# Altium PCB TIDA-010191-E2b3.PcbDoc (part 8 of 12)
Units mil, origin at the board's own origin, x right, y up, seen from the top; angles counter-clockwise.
Board outline 9842.52 x 9842.4 mil, 6 copper layers (Layer 1 - Top Layer, Layer 2 - GND Layer, Layer 3 - Signal, Layer 4 - Signal, Layer 5 - GND, Bottom Layer), stack 59.9 mil thick; 1178 components, 642 nets, 3329 pads, 2967 vias.
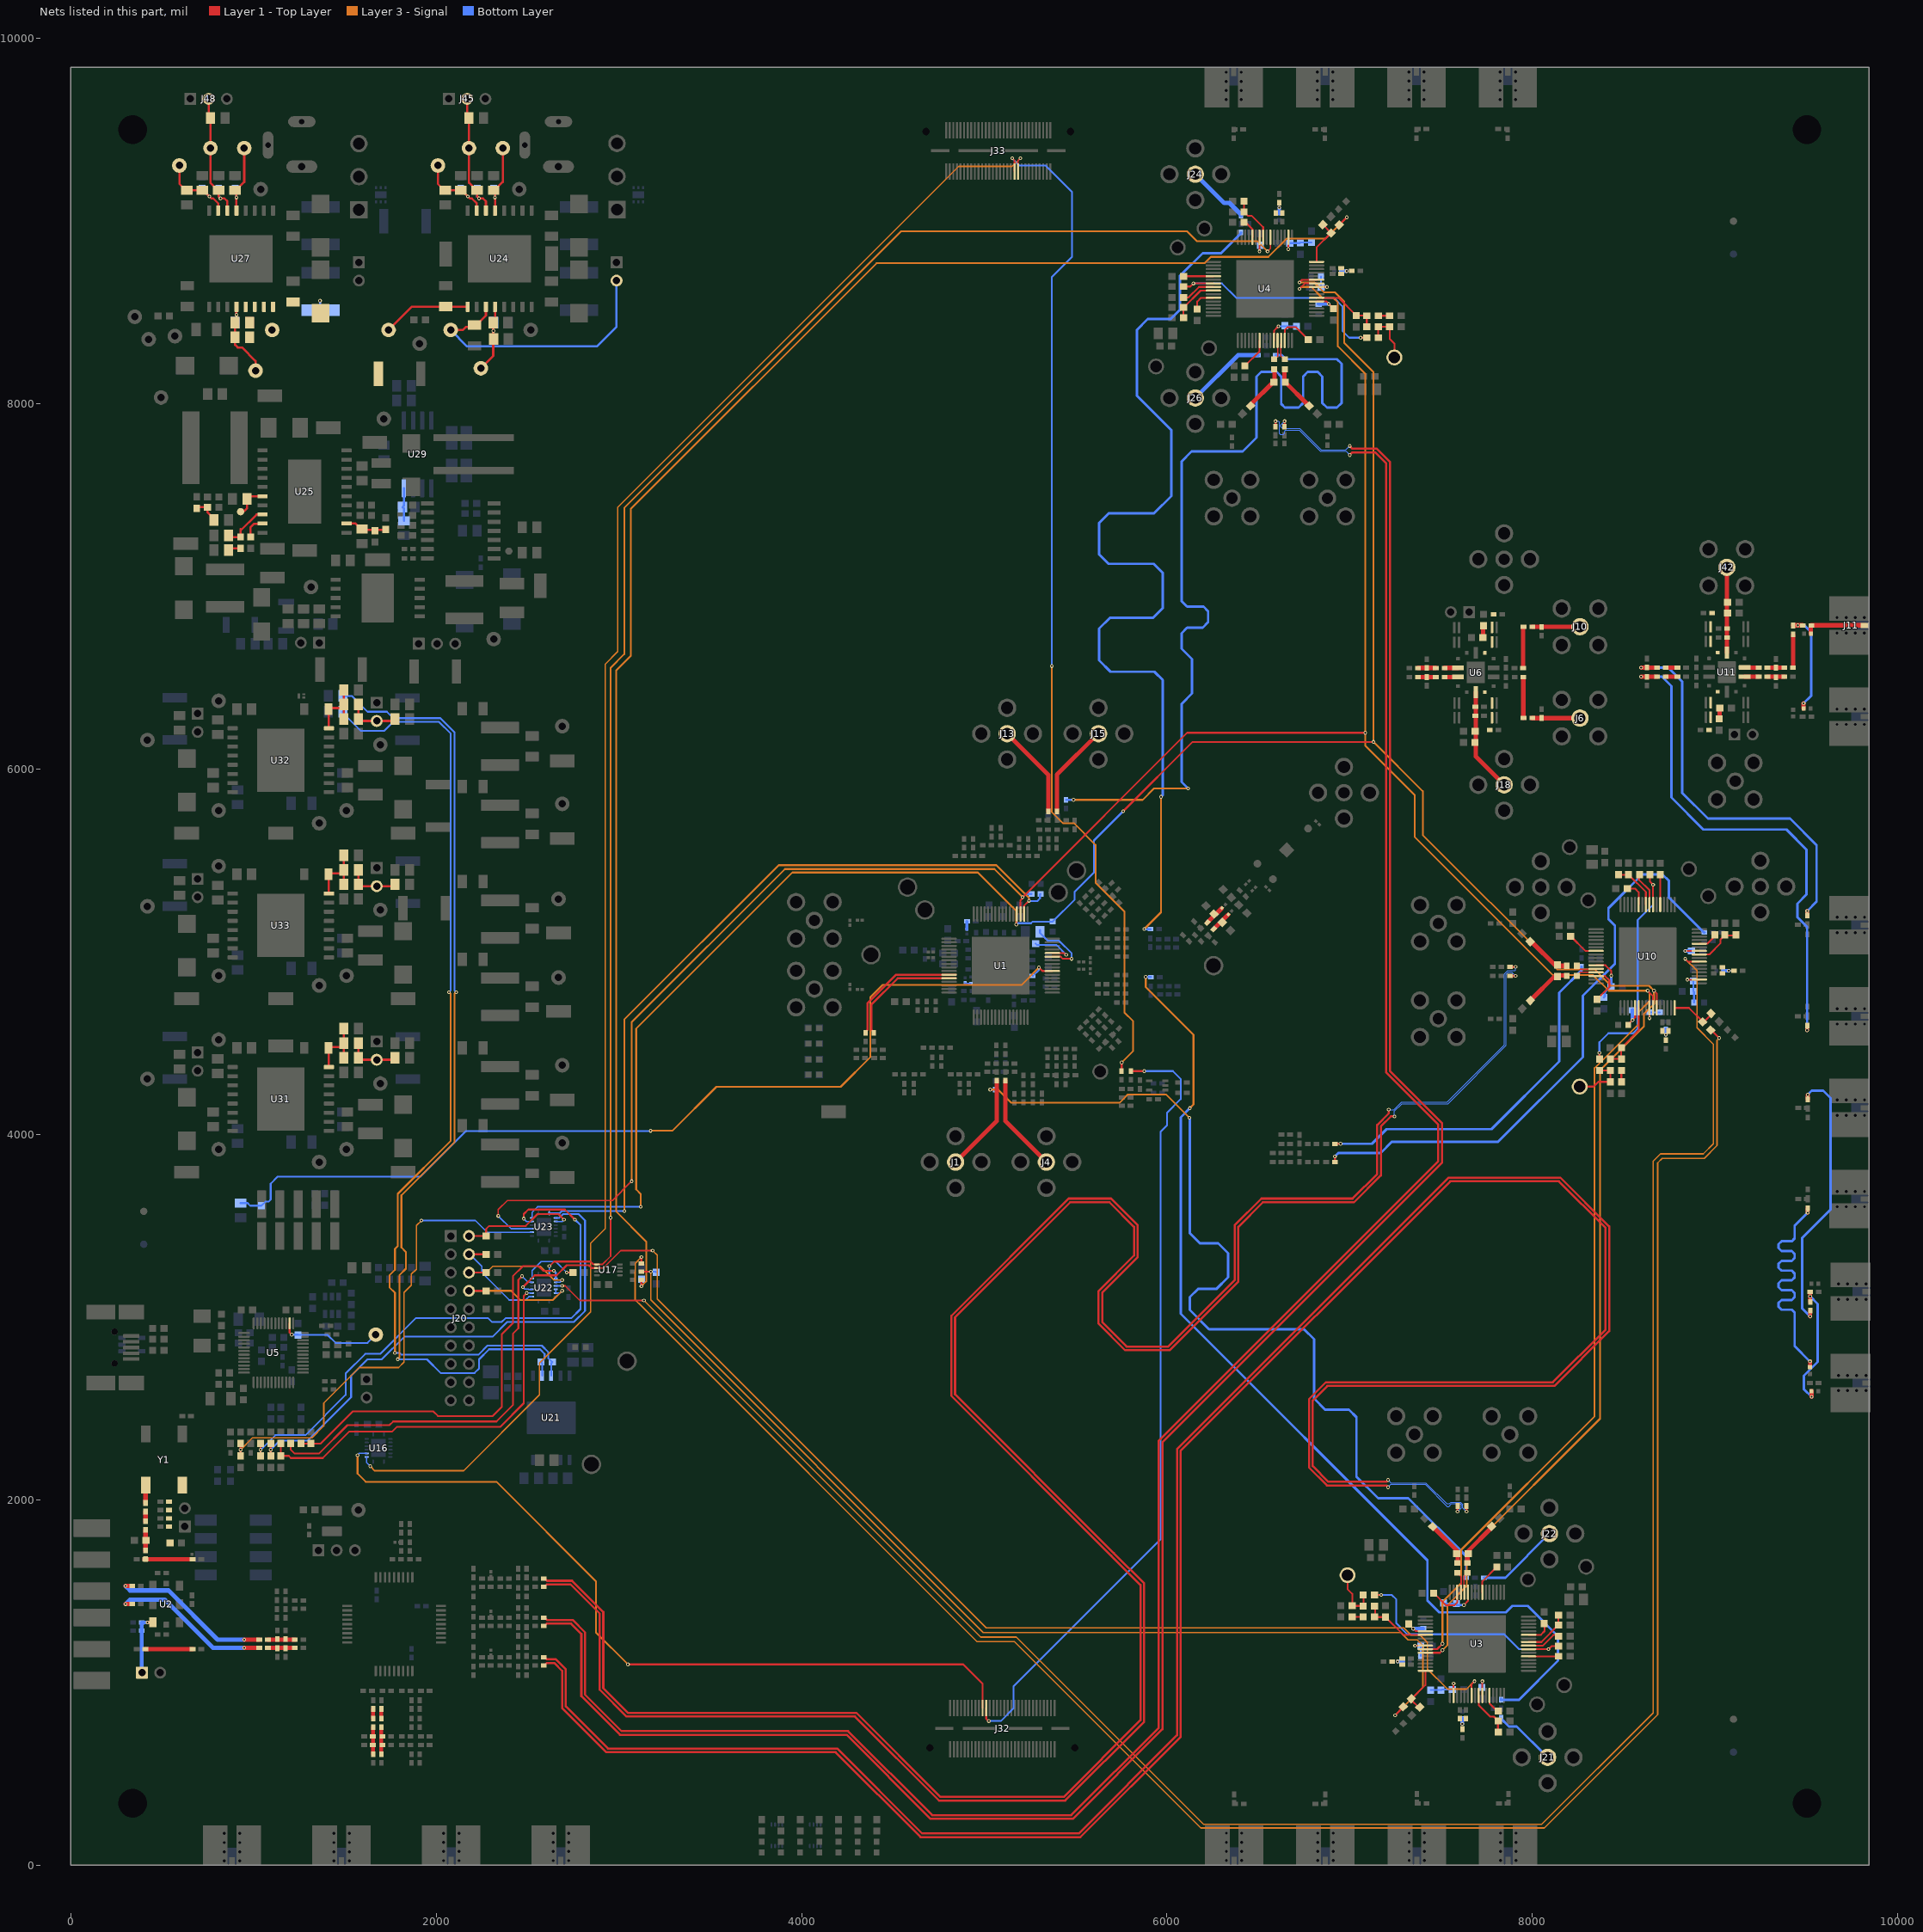
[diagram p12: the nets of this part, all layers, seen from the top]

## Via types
v1: diameter 20, hole 10, Layer 1 - Top Layer to Bottom Layer, tented both sides, 2595 vias
v2: diameter 19.68, hole 7.87, Layer 1 - Top Layer to Bottom Layer, 308 vias
v3: diameter 19.68, hole 7.87, Layer 1 - Top Layer to Bottom Layer, tented both sides, 25 vias
v4: diameter 20, hole 10, Layer 1 - Top Layer to Bottom Layer, 21 vias
v5: diameter 41, hole 25, Layer 1 - Top Layer to Bottom Layer, 10 vias
v6: diameter 24, hole 12, Layer 1 - Top Layer to Bottom Layer, tented both sides, 4 vias
v7: diameter 24, hole 8, Layer 1 - Top Layer to Bottom Layer, tented both sides, 1 vias
v8: diameter 24/24/24/24/24/24 (per signal layer), hole 8, Layer 1 - Top Layer to Bottom Layer, tented both sides, 1 vias
v9: diameter 30, hole 12, Layer 1 - Top Layer to Bottom Layer, tented both sides, 1 vias
v10: diameter 20/20/20/20/20/20 (per signal layer), hole 10, Layer 1 - Top Layer to Bottom Layer, tented both sides, 1 vias

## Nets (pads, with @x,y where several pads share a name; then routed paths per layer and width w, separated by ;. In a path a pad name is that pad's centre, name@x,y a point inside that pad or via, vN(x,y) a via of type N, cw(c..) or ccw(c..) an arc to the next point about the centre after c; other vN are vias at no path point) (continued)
ILMK04832-SP_CSb: R157.2 R187.1 U23.10 | length 2849.3
  Layer 1 - Top Layer w10: R187.1@1095,2241.5 v1(1095,2275) R157.2@1095,2309.09
  Bottom Layer w10: v1(1095,2275) 1145,2325 1297.43,2325 1535,2562.57 1535,2680 1625,2770 1702.2,2770 1826.37,2894.17 2309.17,2894.17 2390,2975 2755,2975 2815,3035 2815,3530 2780,3565 2695,3565 2674.49,3544.49 2655.24,3544.49 U23.10@2654.96,3544.21
ILMK_LMX_CLK: R154.2 R185.1 U23.3 | length 2680.8
  Layer 1 - Top Layer w10: R185.1@930,2241.5 v1(930,2275) R154.2@930,2309.09
  Layer 3 - Signal w8: v1(930,2275) 995,2340 1320,2340 1385,2405 1385,2530 1580,2725 1795,2725 1825,2755 1825,3135 1865,3175 1865,3236.5 1892.2,3263.7 1892.2,3502.2 v1(1920,3530)
  Bottom Layer w8: v1(1920,3530) 2215,3530 2279.53,3465.47 U23.3@2525.04,3465.47
ILMK_LMX_DATA: R156.2 R186.1 U23.6 | length 3113.9
  Layer 1 - Top Layer w10: R186.1@1040,2241.5 v1(1040,2275) R156.2@1040,2309.09 ; v1(2480,3540) 2480,3565 2505,3590 2705,3590 v1(2760,3535)
  Bottom Layer w8: v1(2480,3540) 2495.47,3524.53 U23.6@2525.04,3524.53
  Bottom Layer w10: v1(1040,2275) 1120,2355 1285,2355 1505,2575 1505,2692.43 1612.57,2800 1693.5,2800 1888.5,2995 2285,2995 2305,2975 2360,2975 2380,2995 2740,2995 2790,3045 2790,3505 v1(2760,3535)
ILMX1_CSB: R158.2 R188.1 U22.3 | length 2165.7
  Layer 1 - Top Layer w10: R158.2@1150,2309.09 R188.1@1150,2241.5 1193.5,2241.5 1205,2230 1380,2230 1525,2375 1760,2375 1785,2400 2350,2400 2480,2530 2480,3117.05 v1(2496.48,3133.52)
  Bottom Layer w8: v1(2496.48,3133.52) 2496.97,3133.03 U22.3@2525.04,3133.03
ILMX2_CSB: R181.2 R206.1 U22.10 | length 2249.3
  Layer 1 - Top Layer w10: R181.2@1260,2309.09 R206.1@1315,2309.09 ; R206.1@1315,2309.09 1369.09,2309.09 1545,2485 1985,2485 2010,2460 2310,2460 2360,2510 2360,2907.66 2420,2967.66 2420,3225 2475,3280 2560,3280 2585,3255 v1(2645,3255)
  Bottom Layer w10: v1(2645,3255) 2654.96,3245.04 U22.10@2654.96,3211.77
ILMX_SDO: R159.2 U22.6 | length 2161.5
  Layer 1 - Top Layer w10: R159.2@1205,2309.09 1205,2275 1225,2255 1360,2255 1515,2410 1745,2410 1765,2430 2330,2430 2420,2520 2420,2910 2450,2940 2450,3205 v1(2470,3225)
  Bottom Layer w8: v1(2470,3225) 2502.91,3192.09 U22.6@2525.04,3192.09
IOVLVL: NT2.1 R211.2 R335.1 U1.7 | length 5302.6
  Layer 1 - Top Layer w10: v1(5298.76,4915) 5317.56,4896.2 5325,4896.2 5325.73,4895.47 U1.7@5372.48,4895.47
  Layer 3 - Signal w10: v1(3174,4021) 3293,4021 3534,4262 4214,4262 4377,4425 4377,4754 4442.23,4819.23 5202.99,4819.23 v1(5298.76,4915)
  Bottom Layer w10: NT2.1@930,3625 968.56,3625 982.5,3611.06 R211.2@1045,3611.06 1045,3612.05 1065.82,3632.87 1082.87,3632.87 1095,3645 1095,3732 1133,3770 1914,3770 2164,4020 3173,4020 v1(3174,4021) ; R335.1@5263.62,4870 5267.56,4870 5298.76,4901.2 v1(5298.76,4915)
J1J4_N: J4.1 R6.1 | length 539.6
  Layer 1 - Top Layer w24: R6.1@5115,4296.38 5115,4075 J4.1@5340,3850
J1J4_P: J1.1 R3.1 | length 539.6
  Layer 1 - Top Layer w24: J1.1@4843,3850 5068,4075 R3.1@5068,4296.38
J15J13_N: J13.1 R56.1 | length 519.6
  Layer 1 - Top Layer w24: J13.1@5125,6195 5350,5970 R56.1@5350,5768.62
J15J13_P: J15.1 R54.1 | length 519.6
  Layer 1 - Top Layer w24: R54.1@5397,5768.62 5397,5970 J15.1@5622,6195
J21: J21.1 R246.2 | length 349.8
  Bottom Layer w13.5: R246.2@7827.82,803.75 7871.57,760 7914.13,760 J21.1@8077.91,596.21
  Bottom Layer w24: J21.1@8077.91,582.49 J21.1@8077.91,596.21
J22: J22.1 R249.2 | length 458.6
  Bottom Layer w13.5: R249.2@7734.18,1575.03 7851.54,1575.03 J22.1@8092.82,1816.31
J24: J24.1 R358.2 | length 345.7
  Bottom Layer w24: J24.1@6154.91,9257.44 6312.35,9100 6341.18,9100 6405,9036.18 R358.2@6405,9032.24
J26: J26.1 R360.2 | length 440.1
  Bottom Layer w24: J26.1@6154.91,8032.44 6389.91,8267.44 R360.2@6497.66,8267.44
LMK6_OUT_N: C89.1 R46.2 | length 888.5
  Layer 1 - Top Layer w24: v1(300,1430) R46.2@336.38,1430 ; v1(950,1191) C89.1@1032.38,1191
  Bottom Layer w24: v1(300,1430) 325,1455 515,1455 779,1191 v1(950,1191)
LMK6_OUT_P: C88.1 R45.2 | length 890.5
  Layer 1 - Top Layer w24: v1(300,1530) R45.2@336.38,1530 ; v1(950,1236) C88.1@1032.38,1236
  Bottom Layer w24: v1(300,1530) 325,1505 535.71,1505 804.71,1236 v1(950,1236)
LMK04832-SP_CSb: C18.2 U1.18 U23.9 | length 4295.9
  Layer 1 - Top Layer w10: U1.18@5217.95,5207.48 5217.95,5252.95 v1(5245,5280)
  Layer 3 - Signal w10: v1(3030,3582) 3030,4630 3875,5475 5066.11,5475 5245,5296.11 v1(5245,5280)
  Bottom Layer w10: U23.9@2619.53,3569.8 2675.76,3569.8 2687.96,3582 v1(3030,3582) ; v1@5243.09,5278.09 5289.8,5278.09 5305,5293.29 5305,5314.94 C18.2@5307.5,5317.44
LMK04832-SP_RESET1: J32.41 U16.11 | length 4348
  Layer 1 - Top Layer w10: v1(3050,1100) 4885,1100 4990.86,994.14 J32.41@4990.86,862.12
  Layer 3 - Signal w10: v1(1570,2245) 1570,2145 1615,2100 2330,2100 2875,1555 2875,1275 v1(3050,1100)
  Bottom Layer w8.6: v1(1570,2245) 1580.47,2255.47 U16.11@1620.04,2255.47
LMK04832-SP_RESET2: J33.41 U16.10 | length 9275.4
  Layer 1 - Top Layer w8: J33.41@5184.88,9272.88 5184.88,9332.36 v1(5197.52,9345)
  Layer 3 - Signal w8: v1(1640,2185) 1665,2160 2150,2160 2565,2575 2565,2750 2845,3030 2845,3405 2925,3485 2925,6529.2 2925,6575 2994.08,6644.08 2994.08,7434.08 4860,9300 5152.52,9300 v1(5197.52,9345)
  Bottom Layer w8: U16.10@1620.04,2235.79 1620.04,2204.96 v1(1640,2185)
LMK04832-SP_SYNC1: J32.39 R200.1 | length 4356.2
  Layer 1 - Top Layer w10: J32.39@5010.54,862.12 5010.54,802.64 v1@5023.18,790 ; R200.1@5801.89,4347.72 v1(5875,4347.72)
  Bottom Layer w10: v1(5025,790) 5090,790 5160,860 5160,980 5965,1785 5965,4016.38 6000,4051.38 6000,4120 6075,4195 6075,4305 6032.28,4347.72 v1(5875,4347.72)
LMK04832-SP_SYNC2: J33.39 R202.1 | length 5584.9
  Layer 1 - Top Layer w8: v1(5152.56,9345) 5165.2,9332.36 J33.39@5165.2,9272.88
  Layer 1 - Top Layer w10: R202.1@5751.89,4347.72 v1(5751.89,4395)
  Layer 3 - Signal w10: v1(5370,6565) 5370,5765 5430,5705 5490,5705 5608.7,5586.3 5608.7,5379.8 5767.11,5221.39 5767.11,4667.89 5815,4620 5815,4458.11 v1(5751.89,4395)
  Bottom Layer w10: v1(5152.56,9345) 5192.56,9305 5335,9305 5480,9160 5480,8805.15 5370,8695.15 v1(5370,6565)
LMK_LMX_CLK: C20.2 U1.19 U3.26 U4.26 U10.26 U23.4 | length 16204.4
  Layer 1 - Top Layer w8: v1(2340,3555) 2340,3590 2390,3640 2965,3640 v1(3070,3745)
  Layer 1 - Top Layer w10: U1.19@5198.27,5207.48 5198.27,5283.27 5210,5295 v1(5210,5300) 6110,6200 v1(7085,6200) ; v1(6725,8630) 6754.56,8659.56 U4.26@6818.57,8659.56 ; U3.26@7413.78,1183.43 7477.79,1183.43 v1(7507.35,1212.98) ; v1(8630.5,4787.55) 8660.06,4757.99 U10.26@8660.06,4693.98
  Layer 3 - Signal w10: v1(3070,3745) 3070,4615 3908.94,5453.94 5056.06,5453.94 v1(5210,5300) ; v1(6725,8630) 6735,8640 6790,8640 6850,8580 6910,8580 6935,8555 6935,8315 7085,8165 7085,7995 v1(7085,6200) 7085,6130 7355,5860 7355,5630 8111.72,4873.28 8331.72,4873.28 8417.45,4787.55 v1(8630.5,4787.55) 8640,4778.05 8640,4730 8580,4670 8580,4605 8340,4365 8340,2457.43 7610,1727.43 7610,1545 7507.35,1442.35 v1(7507.35,1212.98)
  Bottom Layer w8: v1(2340,3555) 2409.84,3485.16 U23.4@2525.04,3485.16
  Bottom Layer w10: v1(5210,5300) 5210.47,5300 5227.91,5317.44 C20.2@5259.68,5317.44
LMK_LMX_DATA: C21.2 U1.20 U3.27 U4.27 U10.27 U23.7 | length 16167.3
  Layer 1 - Top Layer w8: v1@5175.73,5151.07 5177.79,5153.13 5177.79,5161.37 5177.85,5161.43 5177.85,5206.75 U1.20@5178.58,5207.48 U1.20@5179.31,5206.75
  Layer 1 - Top Layer w10: v1(5760,5770) 6140,6150 v1(7130,6150) ; v1(6725,8665) 6739.24,8679.24 U4.27@6818.57,8679.24 ; U3.27@7413.78,1163.74 7493.11,1163.74 v1(7507.35,1177.98) ; v1(8665.5,4787.55) 8679.74,4773.3 U10.27@8679.74,4693.98
  Layer 3 - Signal w10: v1(3120,3605.36) 3120,3675 3095,3700 3095,4580 3950,5435 4965,5435 5175.5,5224.5 v1(5175.5,5150.09) ; v1(6725,8665) 6805,8665 6860,8610 6920,8610 6970,8560 6970,8335 7130,8175 7130,8010 v1(7130,6150) 7400,5880 7400,5640 8135,4905 8340,4905 8430,4815 8638.05,4815 v1(8665.5,4787.55) 8665.5,4715.5 8610,4660 8610,4592.57 8370,4352.57 8370,2445 7640,1715 7640,1530 7535,1425 7535,1205.63 v1(7507.35,1177.98)
  Bottom Layer w8: U23.7@2525.04,3544.21 2525.04,3575.04 2555.36,3605.36 v1(3120,3605.36)
  Bottom Layer w10: v1(5175.5,5150.09) 5182.64,5157.23 5255.16,5157.23 5264.14,5166.21 5373.57,5166.21 C21.2@5373.77,5166.41 ; C21.2@5373.57,5166.89 5374.56,5166.89 5495,5287.34 5495,5330 5600,5435 5600,5610 v1(5760,5770)
LMK_OSCin_N: R443.2 U1.44 | length 681.7
  Layer 1 - Top Layer w12: R443.2@4395,4557.38 4395,4562.76 4382,4575.76 4382,4712 4526.1,4856.1 U1.44@4844,4856.1
LMK_OSCin_P: R441.2 U1.43 | length 714.3
  Layer 1 - Top Layer w12: R441.2@4350,4557.38 4350,4562.76 4362,4574.76 4362,4720.28 4517.55,4875.83 U1.43@4844,4875.83
LMK_SCSB: J20.2 R308.2 U23.11 | length 653.9
  Layer 1 - Top Layer w10: J20.2@2180,3445 R308.2@2273.5,3445 2273.5,3483.5 2290,3500 2490,3500 2555,3565 2670,3565 v1(2700,3535)
  Bottom Layer w8: U23.11@2655.1,3524.67 2689.67,3524.67 v1(2700,3535)
LMK_VCXO: C12.1 C87.2 R39.2 R362.1 | length 262.7
  Layer 1 - Top Layer w24: R39.2@405,1674.93 665,1674.93 C12.1@667.74,1674.93
LMX1_CSB: U3.39 U17.6 U22.4 | length 6679.3
  Layer 1 - Top Layer w8: U17.6@2879.93,3269.84 2914.84,3269.84 3010,3365 v1(3185,3365) ; U3.39@7666.73,930.47 7666.73,992.36 v1(7682.35,1007.98)
  Layer 1 - Top Layer w10.5: v1(2475,3165) 2540,3230 2660,3230 2715,3285 2835,3285 2849.91,3270.09 2879.68,3270.09 U17.6@2879.93,3269.84
  Layer 3 - Signal w8: v1(3185,3365) 3210,3340 3210,3100 5010,1300 7295,1300 7335,1260 7385,1260 7425,1220 7425,1075 7535,965 7639.37,965 v1(7682.35,1007.98)
  Bottom Layer w8: v1(2475,3165) 2485.48,3154.52 2505.17,3154.52 2506.98,3152.72 U22.4@2525.04,3152.72
LMX1_OSCin+: C71.2 U3.12 | length 114
  Layer 1 - Top Layer w8: U3.12@7627.36,1495.43 7627.36,1514.24 7625.52,1516.09 7625.52,1582.32 C71.2@7644.15,1600.95
LMX1_OSCin-: C72.2 U3.13 | length 114.8
  Layer 1 - Top Layer w8: C72.2@7588.97,1600.95 7609.52,1580.41 7609.52,1516.09 7607.68,1514.24 U3.13@7607.68,1495.43
LMX1_SCSB: J20.4 R309.2 U22.2 | length 570.2
  Layer 1 - Top Layer w13.5: J20.4@2180,3345 R309.2@2273.5,3345
  Bottom Layer w8: J20.4@2180,3345 2185,3345 2250,3280 2250,3245 2400,3095 2490,3095 2508.35,3113.35 U22.2@2525.04,3113.35
LMX1_SDO: R102.2 R189.2 R218.2 | length 5750.4
  Layer 1 - Top Layer w10.5: R218.2@3123.62,3250 v1(3175,3250) ; v1(7248.62,821.72) R102.2@7290.17,863.27
  Layer 3 - Signal w8: v1(3175,3250) 3175,3095 4995,1275 7280,1275 7320,1235 7370,1235 7400,1205 7400,973.1 v1(7248.62,821.72)
  Bottom Layer w10.5: v1(3175,3250) 3201.5,3250 R189.2@3205,3246.5
LMX1_SYNC: R141.1 R247.2 | length 5129.5
  Layer 3 - Signal w10: v1(5032.31,4246.78) 5075.22,4246.78 5148,4174 5740,4174 5786,4220 5995,4220 v1(6122,4093)
  Bottom Layer w13.5: v1(5032.31,4246.78) R141.1@5056.31,4246.78 ; v1(6122,4093) 6123.24,4091.76 6123.24,4087.16 6124.5,4085.91 6124.5,3460.71 6180.21,3405 6280,3405 6334,3351 6334,3219 6270,3155 6169.02,3155 6124.5,3110.47 6124.5,3040.5 6230,2935 6750,2935 6805,2880 6805,2555 6865,2495 6995,2495 7037.02,2452.98 7037.02,2127.98 7155,2010 7320,2010 7636.93,1693.07 R247.2@7636.93,1575.03
LMX1_SYSREFREQ: R142.2 R245.2 | length 5502.3
  Layer 3 - Signal w10.5: v1(5884,4863) 5884,4808 6145,4547 6145,4165 v1(6125,4145)
  Bottom Layer w10.5: v1(5884,4863) 5884.04,4862.96 R142.2@5912.65,4862.92 R142.2@5912.65,4862.92
  Bottom Layer w13.5: v1(6125,4145) 6075,4095 6075,3020 7425,1670 7425,1450 7490,1385 7855,1385 7890,1420 7975,1420 8140,1255 8140,1120 7926.53,906.53 R245.2@7827.82,906.53 R245.2@7827.82,910.46
LMX2_CSB: U4.39 U17.5 U22.9 | length 8816.6
  Layer 1 - Top Layer w8: U17.5@2879.93,3289.53 2909.53,3289.53 2955,3335 v1(2955,3545) ; v1(6550,8835) 6565.62,8850.62 U4.39@6565.62,8912.51
  Layer 1 - Top Layer w10.5: v1(2620,3280) 2645,3305 2845,3305 2860.47,3289.53 U17.5@2879.93,3289.53
  Layer 3 - Signal w10: v1(2955,3545) 2955,6555 3030,6630 3030,7430 4545,8945 6110,8945 6165,8890 6495,8890 v1(6550,8835)
  Bottom Layer w8: U22.9@2619.53,3237.36 2619.76,3237.6 2619.76,3279.76 v1(2620,3280)
LMX2_OSCin+: C191.2 U4.12 | length 114
  Layer 1 - Top Layer w8: C191.2@6588.2,8242.03 6606.83,8260.67 6606.83,8326.9 6604.99,8328.74 U4.12@6604.99,8347.55
LMX2_OSCin-: C195.2 U4.13 | length 114.8
  Layer 1 - Top Layer w8: U4.13@6624.67,8347.55 6624.67,8328.74 6622.83,8326.9 6622.83,8262.58 C195.2@6643.38,8242.03
LMX2_SCSB: J20.6 R310.2 U22.11 | length 689
  Layer 1 - Top Layer w8: J20.6@2180,3245 R310.2@2273.5,3245
  Layer 3 - Signal w8: J20.6@2180,3245 2275,3245 2310,3280 2570,3280 2646.08,3203.92 v1(2689.86,3203.92)
  Bottom Layer w8: U22.11@2655.1,3192.22 2678.17,3192.22 v1(2689.86,3203.92)
LMX2_SDO: R219.2 R225.2 R313.2 | length 9080.2
  Layer 1 - Top Layer w10.5: v1(3123.62,3170) R219.2@3123.62,3205 ; R313.2@6942.18,8979.71 v1(6983.73,9021.27)
  Layer 3 - Signal w10: v1(3123.62,3170) 3150,3196.38 3150,3415 2985,3580 2985,6343.29 2985,6540 3065,6620 3065,7425 4410,8770 6205,8770 6240,8805 6555,8805 6655,8905 6867.46,8905 v1(6983.73,9021.27)
  Bottom Layer w10.5: v1(3123.62,3170) 3123.62,3207.13 R225.2@3125,3208.5
LMX2_SYNC: R209.2 R359.2 | length 5146.6
  Layer 3 - Signal w10.5: v1(5488.62,5832.62) 5866.62,5832.62 5929,5895 v1(6115,5895)
  Bottom Layer w10.5: R209.2@5448,5832.62 v1(5488.62,5832.62)
  Bottom Layer w13.5: v1(6115,5895) 6080,5930 6080,6357.42 6137,6414.42 6137,6603 6080,6660 6080,6745 6110,6775 6195,6775 6225,6805 6225,6865 6200,6890 6110,6890 6080,6920 6080,7685 6135,7740 6415,7740 6490,7815 6490,8150 6515,8175 6600,8175 6625,8150 6625,8000 6645,7980 6720,7980 6745,8005 6745,8150 6770,8175 6825,8175 6850,8150 6850,8005 6875,7980 6930,7980 6955,8005 6955,8220 6930,8245 6650,8245 6627.56,8267.44 R359.2@6594.91,8267.44
LMX2_SYSREFREQ: R216.2 R355.2 | length 5501.8
  Layer 3 - Signal w10.5: v1(5875,5125) 5967,5217 v1(5967,5849)
  Bottom Layer w12: v1(5875,5125) 5875.08,5125.08 R216.2@5909.92,5125.08
  Bottom Layer w13.5: v1(5967,5849) 5967,5849.38 5976,5858.38 5976,6488.94 5930.94,6534 5691,6534 5628,6597 5628,6770 5686.5,6828.5 5922.5,6828.5 5976,6882 5976,7075 5926.5,7124.5 5679.5,7124.5 5628,7176 5628,7348 5681.94,7401.94 5929.94,7401.94 6023.75,7495.75 6023.75,7856.25 5835,8045 5835,8405 5895,8465 6020,8465 6070,8515 6070,8700 6195,8825 6295.32,8825 6405,8934.68 R355.2@6405,8938.62
LMX3_CSb: U10.39 U22.12 | length 12028.4
  Layer 1 - Top Layer w8: v1(2690,3172.4) 2707.6,3172.4 2787.5,3092.5 v1(3137.5,3092.5) ; v1(8835.5,4962.55) 8851.12,4946.93 U10.39@8913.01,4946.93
  Layer 3 - Signal w8: v1(3137.5,3092.5) 4980,1250 5175.36,1250 6200.36,225 8050,225 8660,835 8660,3855 8700,3895 8935,3895 8990,3950 8990,4495 8900,4585 8900,4898.05 v1(8835.5,4962.55)
  Bottom Layer w8: U22.12@2654.96,3172.4 v1(2690,3172.4)
LMX3_RFoutA3_N: C204.2 R330.2 R478.2 | length 2797.4
  Layer 1 - Top Layer w22: v1(9503.27,4571.55) R478.2@9503.27,4596.63
  Layer 1 - Top Layer w24: v1(8595,6506.75) C204.2@8681.62,6506.75
  Bottom Layer w13.5: v1(8595,6506.75) 8708.25,6506.75 8760,6455 8760,5845 8935,5670 9390,5670 9500,5560 9500,5315 9450,5265 9450,5190 9503.27,5136.73 v1(9503.27,4571.55)
LMX3_RFoutA3_P: C202.2 R266.2 R329.2 | length 2213.3
  Layer 1 - Top Layer w22: R266.2@9503.58,5199.49 v1(9503.58,5224.58)
  Layer 1 - Top Layer w24: v1(8595,6556.75) C202.2@8681.62,6556.75
  Bottom Layer w13.5: v1(8595,6556.75) 8743.25,6556.75 8820,6480 8820,5870 8960,5730 9410,5730 9555,5585 9555,5275.99 v1(9503.58,5224.58)
LMX3_RFoutB3_N: C134.2 R483.2 | length 1484.1
  Layer 1 - Top Layer w22: R483.2@9506.23,4193.12 v1(9506.23,4218.21) ; v1(9519.71,3005) C134.2@9519.71,3036.33
  Bottom Layer w13.5: v1(9506.23,4218.21) 9528.02,4240 9591,4240 9631,4200 9631,3590 9476,3435 9476,3048.71 v1(9519.71,3005)
LMX3_RFoutB3_P: L14.1 R481.2 | length 1490
  Layer 1 - Top Layer w22: v1(9505.84,3572.55) R481.2@9505.84,3597.63 ; L14.1@9519.07,2727.4 v1(9519.07,2758.73)
  Bottom Layer w13.5: v1(9505.84,3572.55) 9435,3501.71 9435,3455 9435,3432.3 9418.95,3416.25 9362.8,3416.25 9346.75,3400.2 9346.75,3378.8 9362.8,3362.75 9418.95,3362.75 9435,3346.7 9435,3325.3 9418.95,3309.25 9362.8,3309.25 9346.75,3293.2 9346.75,3271.8 9362.8,3255.75 9418.95,3255.75 9435,3239.7 9435,3218.3 9418.95,3202.25 9362.8,3202.25 9346.75,3186.2 9346.75,3164.8 9362.8,3148.75 9418.95,3148.75 9435,3132.7 9435,3111.3 9418.95,3095.25 9362.8,3095.25 9346.75,3079.2 9346.75,3057.8 9362.8,3041.75 9418.95,3041.75 9435,3025.7 9435,3015 9435,2842.8 v1(9519.07,2758.73)
LMX3_SCSb: J20.8 R312.2 U22.13 U22.14 | length 704.6
  Layer 1 - Top Layer w10: J20.8@2180,3145 R312.2@2273.5,3145
  Layer 3 - Signal w10: J20.8@2180,3145 2410,3145 2460,3095 2640,3095 v1(2690,3145)
  Bottom Layer w8: U22.13@2654.96,3152.72 U22.14@2654.96,3133.03 2655.24,3133.31 2678.31,3133.31 v1(2690,3145)
LMX3_SDO: R279.2 R381.2 | length 11370.6
  Layer 1 - Top Layer w10.5: R381.2@3123.62,3295 v1(3123.62,3330) ; R279.2@8980.21,4570.37 v1(9021.76,4528.82)
  Layer 3 - Signal w8: v1(3123.62,3330) 3090,3296.38 3090,3250 3089.1,3249.1 3089.1,3095.9 3125,3060 4960,1225 5165,1225 6185,205 8065.35,205 8685,824.64 8685,3845 8710,3870 8940,3870 9010,3940 9010,4517.05 v1(9021.76,4528.82)
LMX3_SYNC: R144.2 R273.2 | length 1984.3
  Layer 1 - Top Layer w12: R144.2@6918.62,3950 v1(6949.53,3950)
  Bottom Layer w13.5: v1(6949.53,3950) 7121.75,3950 7201.75,4030 7776,4030 8146,4400 8146,4777.02 8269.61,4900.62 R273.2@8269.61,4919.37
LMX3_SYSREFREQ: R148.2 R269.2 | length 3302.4
  Layer 1 - Top Layer w12: R148.2@6918.62,3850 v1(6918.62,3880.91)
  Bottom Layer w13.5: v1(6918.62,3880.91) 6937.72,3900 7170,3900 7230,3960 7811,3960 8276,4425 8276,4760 8451,4935 8451,5145 8416,5180 8416,5240 8601,5425 8711,5425 8746,5390 8746,5298.63 8937.13,5107.5 R269.2@8941.06,5107.5
LMX2615-SP_1_REF_N: R243.2 R471.2 | length 12572
  Layer 1 - Top Layer w12: R471.2@2588.62,1095 2592.56,1095 2605.56,1108 2647,1108 2690,1065 2690,861.72 2931.72,620 4186.72,620 4651.72,155 5526.13,155 6075,703.87 6075,2270 7550,3745 8144.13,3745 8400,3489.13 8400,2933.28 8111.72,2645 6869.71,2645 6777,2552.29 6777,2178 6875,2080 7200,2080 v1(7210,2070) ; v1(7589.94,1936.78) R243.2@7589.94,1967.68
  Bottom Layer w4.25: v1(7210,2070) 7225.5,2085.5 7412.48,2085.5 7533.98,1964 7542,1964 7558,1980 7603.5,1980 7610.39,1973.11 7610.39,1957.23 v1(7589.94,1936.78)
LMX2615-SP_1_REF_P: R239.2 R473.2 | length 12579.7
  Layer 1 - Top Layer w12: R473.2@2588.62,1140 2595,1140 2607,1128 2655.28,1128 2710,1073.28 2710,870 2940,640 4195,640 4660,175 5517.84,175 6055,712.16 6055,2278.28 7541.72,3765 8152.41,3765 8420,3497.41 8420,2925 8120,2625 6878,2625 6797,2544 6797,2186.28 6883.28,2100 7200,2100 v1(7210,2110) ; v1(7639.44,1936.78) R239.2@7639.44,1967.68
  Bottom Layer w4.25: v1(7210,2110) 7226,2094 7416,2094 7530,1980 7545.98,1980 7554.48,1988.5 7607.02,1988.5 7618.89,1976.63 7618.89,1957.33 v1(7639.44,1936.78)
LMX2615-SP_2_REF_N: R352.2 R463.2 | length 12689.7
  Layer 1 - Top Layer w12: R463.2@2588.62,1310 2592.56,1310 2605.56,1323 2738.72,1323 2795,1266.72 2795,926.72 3006.72,715 4246.72,715 4706.72,255 5484.71,255 5975,745.29 5975,2316.42 7504.37,3845.79 7504.37,3862.36 7504.37,4063.91 7220,4348.28 7220,7683.28 7148.28,7755 7015,7755 v1(7000,7770) ; R352.2@6643.38,7874.63 v1(6643.38,7905.54)
  Bottom Layer w4.25: v1(6643.38,7905.54) 6622.93,7885.09 6622.93,7874.55 6632.47,7865 6727.02,7865 6843.02,7749 6979,7749 v1(7000,7770)
LMX2615-SP_2_REF_P: R331.2 R461.2 | length 12690.4
  Layer 1 - Top Layer w12: R461.2@2588.62,1355 2595,1355 2607,1343 2747,1343 2815,1275 2815,935 3015,735 4255,735 4715,275 5476.42,275 5955,753.58 5955,2324.71 7484.37,3854.08 7484.37,4055.63 7200,4340 7200,7675 7140,7735 7015,7735 v1(7000,7720) ; R331.2@6593.88,7874.63 v1(6593.88,7905.54)
  Bottom Layer w4.25: v1(6593.88,7905.54) 6609.46,7905.54 6614.43,7900.57 6614.43,7838.57 6620,7833 6636,7833 6643,7840 6643,7850 6649.5,7856.5 6723.5,7856.5 6839.5,7740.5 6979.5,7740.5 v1(7000,7720)
LMX2615-SP_3_REF_N: R319.2 R453.2 | length 12570.5
  Layer 1 - Top Layer w12: R453.2@2588.62,1525 2592.56,1525 2605.56,1538 2735.62,1538 2895,1378.62 2895,961.72 3041.72,815 4291.72,815 4751.72,355 5443.28,355 5875,786.72 5875,1543.28 5709.26,1709.02 4840,2578.28 4840,3000 5470,3630 5685,3630 5820,3495 5820,3338.28 5625,3143.28 5625,2965.72 5770.72,2820 6015,2820 6390,3195 6390,3495 6525,3630 7023.28,3630 7170,3776.72 7170,4045 7225,4100 v1(7245,4100) ; R319.2@7876.8,4869.1 v1(7907.7,4869.1)
  Bottom Layer w4.25: v1(7245,4100) 7245,4127.98 7287.02,4170 7537.02,4170 7855,4487.98 7855,4876.89 7867.66,4889.55 7887.25,4889.55 v1(7907.7,4869.1)
LMX2615-SP_3_REF_P: R272.2 R451.2 | length 12570.6
  Layer 1 - Top Layer w12: R451.2@2588.62,1570 2595,1570 2607,1558 2743.91,1558 2915,1386.91 2915,970 3050,835 4300,835 4760,375 5435,375 5855,795 5855,1535 5695.12,1694.88 4820,2570 4820,3008.28 5461.72,3650 5693.28,3650 5840,3503.28 5840,3330 5645,3135 5645,2974 5779,2840 6006.72,2840 6370,3203.28 6370,3503.28 6516.72,3650 7015,3650 7150,3785 7150,4053.28 7213.36,4116.64 v1(7213.36,4136.64) ; R272.2@7876.8,4918.1 v1(7907.7,4918.1)
  Bottom Layer w4.25: v1(7213.36,4136.64) 7241.64,4136.64 7283.5,4178.5 7533.5,4178.5 7846.5,4491.5 7846.5,4880.41 7864.14,4898.05 7904.05,4898.05 7907.7,4901.7 v1@7907.7,4918.6
LMX_OSCin3+: C193.2 U10.12 | length 114
  Layer 1 - Top Layer w8: C193.2@8242.53,4924.35 8261.16,4905.72 8327.39,4905.72 8329.24,4907.56 U10.12@8348.05,4907.56
LMX_OSCin3-: C194.2 U10.13 | length 114.8
  Layer 1 - Top Layer w8: C194.2@8242.53,4869.17 8263.07,4889.72 8327.39,4889.72 8329.24,4887.87 U10.13@8348.05,4887.87
LMX_SDO: R207.2 U22.7 | length 312.3
  Layer 1 - Top Layer w8: v1(2715,3245) R207.2@2748.5,3245
  Bottom Layer w8: U22.7@2525.04,3211.77 2525.04,3255.04 2575,3305 2655,3305 v1(2715,3245)
MUXOUT1: R102.1 R105.2 U3.32 | length 254.5
  Layer 1 - Top Layer w10: R105.2@7379.72,862.18 7334.72,907.18 7334.72,907.81 7413.78,986.88 U3.32@7413.78,1065.31
MUXOUT2: R313.1 R314.2 U4.32 | length 254.5
  Layer 1 - Top Layer w10: U4.32@6818.57,8777.67 6818.57,8856.11 R313.1@6897.63,8935.17 6897.63,8935.81 R314.2@6852.63,8980.81
MUXout3: R279.1 R294.2 U10.32 | length 254.5
  Layer 1 - Top Layer w10: U10.32@8778.17,4693.98 8856.6,4693.98 8935.67,4614.91 8936.3,4614.91 R294.2@8981.3,4659.91
NetC8_1: C8.1 R28.2 | length 35.4
  Bottom Layer w8: C8.1@4894.36,4832.27 4894.36,4831.49 4898.63,4827.22 4914.39,4827.22 4914.95,4826.66 R28.2@4927.01,4826.66
NetC9_1: C9.1 R37.2 | length 259.1
  Layer 1 - Top Layer w24: R37.2@408.62,1183.92 C9.1@667.74,1183.92
NetC13_2: C13.2 U1.11 | length 380.6
  Layer 1 - Top Layer w10: U1.11@5377.48,4974.21 U1.11@5372.48,4974.21 5372.83,4974.56 5418.15,4974.56 5430.22,4962.49 v1(5478.28,4962.49)
  Bottom Layer w10: C13.2@5305,5110 5305,5104.66 5347.78,5061.89 5408.67,5061.89 5478.28,4992.28 v1(5478.28,4962.49) ; C13.2@5305,5110.32 C13.2@5305,5120
NetC14_1: C14.1 U1.12 | length 271.7
  Layer 1 - Top Layer w10: U1.12@5372.13,4994.24 U1.12@5372.48,4993.9 5436.24,4993.9 5445.48,4984.66 v1(5448.19,4984.66)
  Bottom Layer w10: C14.1@5281.5,5045 5287.62,5038.88 5393.97,5038.88 v1(5448.19,4984.66)
NetC17_2: C17.2 R52.2 | length 45.8
  Bottom Layer w15: R52.2@4905.77,5125.05 R52.2@4905,5124.29 4905,5167.5 C17.2@4906.08,5168.58
NetC19_2: C19.2 C22.2 C83.2 C84.2 L13.1 Y1.4
NetC38_1: C38.1 R103.2 R110.2 | length 110.4
  Layer 1 - Top Layer w24: C38.1@6255.44,5125.4 6297.52,5167.48 R103.2@6333.52,5203.48
NetC39_1: C39.1 R119.1 R120.2 | length 110.4
  Layer 1 - Top Layer w24: C39.1@6220.44,5160.4 R120.2@6298.52,5238.48
NetC45_1: C45.1 L11.2 R82.2 R86.1 | length 30.3
  Bottom Layer w20: v1(7616,774) L11.2@7616,804.3
NetC46_2: C46.2 R91.1 U3.57 | length 256.9
  Layer 1 - Top Layer w10: U3.57@7978.74,1222.8 8048.51,1222.8 8141.26,1315.54 8142.24,1315.54 R91.1@8142.24,1370.54
NetC47_2: C47.2 R89.1 U3.41 | length 253.6
  Layer 1 - Top Layer w10: U3.41@7706.1,930.47 7706.1,875.98 7768.1,813.98 7788.87,813.98 7809.87,792.98 7810.86,792.98 R89.1@7810.86,732.98
NetC49_2: C49.2 R88.2 U3.25 | length 145.4
  Layer 1 - Top Layer w10: v1(7357.35,1203.11) U3.25@7413.78,1203.11
  Bottom Layer w10: v1(7357.35,1203.11) 7389.31,1203.11 R88.2@7389.31,1146.12
NetC50_2: C50.2 R87.2 R235.2 U3.34 | length 221.6
  Layer 1 - Top Layer w10: U3.34@7568.31,930.47 v1(7568.35,995.98)
  Bottom Layer w10: C50.2@7442.35,959.48 7502.35,959.48 7505.86,962.98 R235.2@7560.86,962.98 7568.35,970.48 v1(7568.35,995.98)
NetC55_2: C55.2 R85.2 U3.21 | length 163.5
  Layer 1 - Top Layer w10: C55.2@7322.35,1321.49 C55.2@7322.35,1321 7322.35,1320.5 v1(7347.29,1295.56) 7361,1281.85 U3.21@7413.78,1281.85
  Bottom Layer w20: v1(7347.29,1295.56) 7402.22,1295.56 R85.2@7402.35,1295.42
NetC56_2: C56.2 R83.2 U3.11 | length 192.7
  Layer 1 - Top Layer w10: v1(7625,1425) 7647.05,1447.05 U3.11@7647.05,1495.43
  Bottom Layer w10: R83.2@7512.98,1436.15 7515.63,1433.5 C56.2@7585,1433.5 ; C56.2@7585,1425 v1(7625,1425)
NetC58_2: C58.2 R94.1 U3.55 | length 1318.7
  Layer 1 - Top Layer w10: R94.1@7138.94,1480.54 v1(7172.35,1480.54) ; U3.55@7978.74,1183.43 v1(8087.79,1183.43) 8104.91,1200.54 C58.2@8142.24,1200.54
  Bottom Layer w10: v1(7172.35,1480.54) 7229.46,1480.54 7255,1455 7255,1325 7315,1265 7845,1265 7926.57,1183.43 v1(8087.79,1183.43)
NetC59_1: C59.1 R94.2 R95.2 Vtune_TP1.1 | length 301.4
  Layer 1 - Top Layer w10: Vtune_TP1.1@6988.06,1588.51 6988.06,1512.28 7013.94,1486.39 C59.1@7013.94,1420.54 7014.47,1420.02 7075.95,1420.02 R94.2@7075.95,1480.54
NetC60_1: C60.1 C62.1 R95.1 U3.22 | length 375.6
  Layer 1 - Top Layer w10: R95.1@7138.94,1420.02 7138.94,1360.54 7140.44,1359.05 7197.45,1359.05 7197.45,1358.06 7293.34,1262.17 U3.22@7413.78,1262.17
NetC60_2: C60.2 R96.1 | length 62
  Layer 1 - Top Layer w10: R96.1@7013.94,1360.54 C60.2@7075.95,1360.54
NetC61_1: C61.1 L12.2 R93.2 R97.1 | length 30.3
  Bottom Layer w20: v1(7261.2,1116.31) L12.2@7291.5,1116.31
NetC65_1: C65.1 R124.1 | length 220
  Layer 1 - Top Layer w24: C65.1@7949.93,6282.18 R124.1@7949.93,6502.18
NetC65_2: C65.2 J6.1 R123.2 | length 261.4
  Layer 1 - Top Layer w24: C65.2@7998.62,6280 J6.1@8260,6280
NetC66_1: C66.1 C67.1 R121.1 | length 97.8
  Layer 1 - Top Layer w24: R121.1@7373.62,6505 C66.1@7471.38,6505
NetC66_2: C66.2 U6.13 | length 73.9
  Layer 1 - Top Layer w24: C66.2@7518.62,6505 U6.13@7592.56,6505
NetC68_1: C68.1 C70.1 R131.1 | length 97.8
  Layer 1 - Top Layer w24: R131.1@7373.62,6555 C70.1@7471.38,6555
NetC69_1: C69.1 R125.1 | length 220
  Layer 1 - Top Layer w24: R125.1@7948.62,6557.82 C69.1@7948.62,6777.82
NetC69_2: C69.2 J10.1 R129.2 | length 261.4
  Layer 1 - Top Layer w24: C69.2@7998.62,6780 J10.1@8260,6780
NetC70_2: C70.2 U6.12 | length 73.9
  Layer 1 - Top Layer w24: C70.2@7518.62,6555 U6.12@7592.56,6555
NetC71_1: C71.1 R107.2 R109.2 | length 252.3
  Layer 1 - Top Layer w24: C71.1@7644.15,1656.07 7644.15,1716.47 R107.2@7779.88,1852.2
NetC72_1: C72.1 R109.1 R112.1 | length 251.9
  Layer 1 - Top Layer w24: R112.1@7457.42,1852.22 7590.47,1719.17 7590.47,1657.57 C72.1@7588.97,1656.07
NetC73_2: C73.2 C74.1 R133.2 U6.8
NetC75_1: C75.1 C76.2 R134.2 U6.3
NetC77_1: C77.1 J18.1 R137.2 R139.2 R140.2 U6.2 | length 571.9
  Layer 1 - Top Layer w24: U6.2@7690,6422.72 7690,6341.65 7690,6207.18 7690,6070 J18.1@7845,5915
NetC78_1: C78.1 R138.1 | length 60
  Layer 1 - Top Layer w22: R138.1@7727.99,6726.65 7729.74,6728.41 7729.74,6783.41 C78.1@7731.49,6785.16
NetC86_1: C86.1 Y1.3 | length 98.2
  Layer 1 - Top Layer w24: C86.1@410,1983.62 410,2080.04 Y1.3@411.26,2081.3
NetC86_2: C86.2 R170.2 | length 52.8
  Layer 1 - Top Layer w24: R170.2@410,1883.62 C86.2@410,1936.38
NetC87_1: C87.1 R170.1 R171.2 | length 112.8
  Layer 1 - Top Layer w24: C87.1@410,1723.62 R170.1@410,1836.38
NetC88_2: C88.2 R177.2 R180.1 R270.1 | length 146.8
  Layer 1 - Top Layer w24: C88.2@1079.62,1236 R180.1@1226.38,1236
NetC89_2: C89.2 R179.2 R220.1 R299.1 | length 146.8
  Layer 1 - Top Layer w24: C89.2@1079.62,1191 R220.1@1226.38,1191
NetC92_1: C92.1 R395.1 R398.1 R403.2 | length 147.8
  Layer 1 - Top Layer w22: R398.1@1700,608.62 1700,705 C92.1@1700,756.38
NetC92_2: C92.2 R397.2 | length 52.8
  Layer 1 - Top Layer w22: C92.2@1700,803.62 R397.2@1700,856.38
NetC98_2: C98.2 U3.14 | length 220.3
  Layer 1 - Top Layer w10: C98.2@7458.94,1490.54 7459.93,1490.54 7527.49,1422.98 7572.35,1422.98 7587.99,1438.62 U3.14@7587.99,1495.43
NetC99_1: C99.1 U3.56 | length 187.3
  Layer 1 - Top Layer w10: U3.56@7978.74,1203.11 8057.48,1203.11 8114.91,1260.54 C99.1@8142.24,1260.54
NetC100_2: C100.2 U3.59 | length 138
  Layer 1 - Top Layer w10: U3.59@7978.74,1262.17 8046.53,1262.17 8066.74,1282.37 C100.2@8066.74,1324.05
NetC101_1: C101.1 U3.44 | length 112.1
  Layer 1 - Top Layer w10: U3.44@7765.16,930.47 7765.16,886.18 7812.4,838.93 C101.1@7812.4,837.93
NetC102_1: C102.1 U3.7 | length 172.3
  Layer 1 - Top Layer w10: U3.7@7725.79,1495.43 7725.79,1554.3 7805.28,1633.8 C102.1@7805.28,1634.78
NetC103_1: C103.1 U3.42 | length 112.4
  Layer 1 - Top Layer w10: U3.42@7725.79,930.47 v1(7725.79,1007.98)
  Bottom Layer w10: C103.1@7722.35,974.48 7725.79,977.92 v1(7725.79,1007.98)
NetC104_1: C104.1 U3.53 | length 163.5
  Layer 1 - Top Layer w10: U3.53@7978.74,1144.06 8119.45,1144.06 8119.56,1144.16 C104.1@8142.24,1144.16
NetC105_1: C105.1 J11.1 L39.2 | length 336.9
  Layer 1 - Top Layer w24: L39.2@9523.49,6742.98 C105.1@9523.49,6787.08 ; C105.1@9526.27,6787.89 J11.1@9819.06,6787.89
NetC105_2: C105.2 C133.1 L37.1 | length 574.7
  Layer 1 - Top Layer w24: C133.1@9426.36,6787.94 v1(9452.67,6787.94) C105.2@9478.97,6787.94 ; L37.1@9483.74,6333.09 v1(9483.74,6361.08)
  Bottom Layer w13.5: v1(9452.67,6787.94) 9487.06,6787.94 9525,6750 9525,6402.34 v1(9483.74,6361.08)
NetC113_2: C113.2 U5.38 VCCCORE.1 | length 564
  Layer 1 - Top Layer w10: U5.38@1198.58,2967.01 1198.58,2916.42 v1(1210,2905)
  Bottom Layer w10: v1(1210,2905) 1243.5,2905 C113.2@1245,2903.5 1406.27,2903.5 1449.77,2860 1625,2860 VCCCORE.1@1670,2905
NetC128_2: C128.2 R253.1 U4.57 | length 256.9
  Layer 1 - Top Layer w10: R253.1@6090.11,8472.44 C128.2@6090.11,8527.44 6091.09,8527.44 6183.84,8620.19 U4.57@6253.61,8620.19
NetC129_2: C129.2 R257.2 U4.11 | length 186.2
  Layer 1 - Top Layer w10: U4.11@6585.3,8347.55 6585.3,8400.3 v1(6610,8425)
  Bottom Layer w10: v1(6610,8425) R257.2@6708.5,8425
NetC130_2: C130.2 R256.2 U4.21 | length 163.5
  Layer 1 - Top Layer w10: U4.21@6818.57,8561.13 6871.35,8561.13 v1(6885.06,8547.42) 6910,8522.48 C130.2@6910,8521.5
  Bottom Layer w20: R256.2@6830,8547.56 6830.14,8547.42 v1(6885.06,8547.42)
NetC131_2: C131.2 L18.2 R258.2 R260.1 | length 30.3
  Bottom Layer w20: L18.2@6615,9043.7 v1(6615,9074)
NetC132_1: C132.1 R396.1 R400.1 R404.2 | length 147.8
  Layer 1 - Top Layer w22: R400.1@1655,608.62 C132.1@1655,756.38
NetC132_2: C132.2 R399.2 | length 52.8
  Layer 1 - Top Layer w22: C132.2@1655,803.62 R399.2@1655,856.38
NetC133_2: C133.2 R373.2 | length 179
  Layer 1 - Top Layer w24: R373.2@9426.06,6556.75 C133.2@9426.06,6735.79
NetC134_1: C134.1 C333.2 L40.1 | length 703.7
  Layer 1 - Top Layer w22: C333.2@9518.97,3140.15 9519.71,3139.41 v1(9519.71,3114.9) C134.1@9519.71,3083.57 ; v1(9527.47,2564.72) L40.1@9527.47,2596.05
  Bottom Layer w13.5: v1(9519.71,3114.9) 9561,3073.61 9561,2755 9486,2680 9486,2606.19 v1(9527.47,2564.72)
NetC135_1: C135.1 J49.2 R505.1 R509.2 | length 288.3
  Layer 1 - Top Layer w12: R509.2@1575,4420 C135.1@1575,4500 ; R509.2@1575,4420 1585,4410 1765,4410 R505.1@1775,4420
NetC135_2: C135.2 C285.1 R509.1 R511.2 U31.16 | length 356.8
  Layer 1 - Top Layer w12: U31.16@1413.5,4370 1413.5,4473.43 C285.1@1411.93,4475 1417.4,4480.47 1481,4480.47 C135.2@1495,4494.47 ; R509.1@1495,4420 C135.2@1495,4494.47 ; R511.2@1495,4580 C135.2@1495,4500 C135.2@1495,4494.47
NetC136_1: C136.1 J51.2 R517.1 R520.2 | length 289.2
  Layer 1 - Top Layer w12: R520.2@1575,6274.53 C136.1@1575,6355.47 ; R520.2@1575,6274.53 1585,6264.53 J51.2@1675,6264.53 1765,6264.53 R517.1@1775,6274.53
NetC136_2: C136.2 C304.1 R520.1 R522.2 U32.16 | length 362.7
  Layer 1 - Top Layer w12: U32.16@1413.5,6224.53 1413.5,6327.96 C304.1@1411.93,6329.53 1417.4,6335 1481.03,6335 1495,6348.97 C136.2@1495,6355.47 R522.2@1495,6434 ; R520.1@1495,6274.53 C136.2@1495,6355.47
NetC137_1: C137.1 J53.2 R530.1 R533.2 | length 288.3
  Layer 1 - Top Layer w12: R533.2@1575,5370 C137.1@1575,5450 ; R533.2@1575,5370 1585,5360 1765,5360 R530.1@1775,5370
NetC137_2: C137.2 C344.1 R533.1 R535.2 U33.16 | length 356.8
  Layer 1 - Top Layer w12: U33.16@1413.5,5320 1413.5,5423.43 C344.1@1411.93,5425 1417.4,5430.47 1481,5430.47 C137.2@1495,5444.47 ; R533.1@1495,5370 C137.2@1495,5444.47 ; R535.2@1495,5530 C137.2@1495,5450 C137.2@1495,5444.47
NetC138_2: C138.2 R255.2 U4.25 | length 146.2
  Layer 1 - Top Layer w10: U4.25@6818.57,8639.87 v1(6875,8639.87)
  Bottom Layer w10: R255.2@6842.46,8697.44 6843.04,8696.87 C138.2@6843.04,8639.87 v1(6875,8639.87)
NetC139_2: C139.2 R254.1 U4.41 | length 253.6
  Layer 1 - Top Layer w10: R254.1@6421.5,9110 C139.2@6421.5,9050 6422.48,9050 6443.48,9029 6464.25,9029 6526.25,8967 U4.41@6526.25,8912.51
NetC140_2: C140.2 R251.2 R252.2 U4.34 | length 221.6
  Layer 1 - Top Layer w10: v1(6664,8847) U4.34@6664.04,8912.51
  Bottom Layer w10: v1(6664,8847) 6664,8872.5 R252.2@6671.5,8880 6726.5,8880 6730,8883.5 C140.2@6790,8883.5
NetC143_2: C143.2 U4.14 | length 220.3
  Layer 1 - Top Layer w10: U4.14@6644.36,8347.55 6644.36,8404.36 6660,8420 6704.87,8420 6772.43,8352.44 C143.2@6773.41,8352.44
NetC144_1: C144.1 U4.56 | length 187.3
  Layer 1 - Top Layer w10: C144.1@6090.11,8582.44 6117.44,8582.44 6174.87,8639.87 U4.56@6253.61,8639.87
NetC145_2: C145.2 U4.59 | length 138
  Layer 1 - Top Layer w10: C145.2@6165.61,8518.94 6165.61,8560.61 6185.82,8580.82 U4.59@6253.61,8580.82
NetC146_1: C146.1 C148.1 R320.1 U4.22 | length 375.6
  Layer 1 - Top Layer w10: U4.22@6818.57,8580.82 6939.01,8580.82 7034.91,8484.92 C148.1@7034.91,8483.94 7091.91,8483.94 C146.1@7093.41,8482.44 R320.1@7093.41,8422.97
NetC146_2: C146.2 R322.1 | length 62
  Layer 1 - Top Layer w10: C146.2@7156.4,8482.44 R322.1@7218.41,8482.44
NetC147_1: C147.1 U4.44 | length 112.1
  Layer 1 - Top Layer w10: C147.1@6419.95,9005.05 6419.95,9004.05 6467.19,8956.81 U4.44@6467.19,8912.51
NetC149_1: C149.1 R320.2 R321.2 Vtune_TP2.1 | length 301.4
  Layer 1 - Top Layer w10: R321.2@7156.4,8362.44 R320.2@7156.4,8422.97 7217.89,8422.97 C149.1@7218.41,8422.44 7218.41,8356.59 7244.3,8330.7 Vtune_TP2.1@7244.3,8254.48
NetC150_2: C150.2 R321.1 U4.55 | length 1321.6
  Layer 1 - Top Layer w10: C150.2@6090.11,8642.44 6127.44,8642.44 v1(6144.56,8659.56) U4.55@6253.61,8659.56 ; v1(7060,8362.44) R321.1@7093.41,8362.44
  Bottom Layer w10: v1(6144.56,8659.56) 6300.44,8659.56 6380,8580 6915,8580 6960,8535 6960,8400 6997.56,8362.44 v1(7060,8362.44)
NetC151_1: C151.1 U4.7 | length 172.3
  Layer 1 - Top Layer w10: C151.1@6427.07,8208.2 6427.07,8209.19 6506.56,8288.68 U4.7@6506.56,8347.55
NetC152_1: C152.1 U4.42 | length 112.4
  Layer 1 - Top Layer w10: v1(6506.56,8835) U4.42@6506.56,8912.51
  Bottom Layer w10: v1(6506.56,8835) 6506.56,8865.07 C152.1@6510,8868.5
NetC154_2: C154.2 R226.2 R372.2 U10.34 | length 221.6
  Layer 1 - Top Layer w10: v1(8847.5,4848.55) U10.34@8913.01,4848.5
  Bottom Layer w10: v1(8847.5,4848.55) 8873,4848.55 R372.2@8880.5,4841.05 8880.5,4786.05 8884,4782.55 C154.2@8884,4722.55
NetC155_2: C155.2 R227.2 U10.11 | length 257
  Layer 1 - Top Layer w10: U10.11@8348.05,4927.24 8399.89,4927.24 8431,4896.13 v1(8431,4870)
  Bottom Layer w15: R227.2@8391,4751.5 8396,4756.5 8396,4780 8431,4815 v1(8431,4870)
NetC156_2: C156.2 L21.2 R224.2 R230.1 | length 30.3
  Bottom Layer w20: L21.2@9044.2,4897.55 v1(9074.5,4897.55)
NetC157_2: C157.2 R228.2 U10.21 | length 163.5
  Layer 1 - Top Layer w10: C157.2@8521.99,4602.55 8522.98,4602.55 v1(8547.92,4627.49) 8561.63,4641.2 U10.21@8561.63,4693.98
  Bottom Layer w20: v1(8547.92,4627.49) 8547.92,4682.41 R228.2@8548.06,4682.55
NetC159_1: C159.1 R231.2 U10.25 | length 145.4
  Layer 1 - Top Layer w10: v1(8640.37,4637.55) U10.25@8640.37,4693.98
  Bottom Layer w10: v1(8640.37,4637.55) C159.1@8640.37,4669.51 R231.2@8697.36,4669.51
NetC164_2: C164.2 R232.1 U10.41 | length 253.6
  Layer 1 - Top Layer w10: U10.41@8913.01,4986.3 8967.5,4986.3 9029.5,5048.3 9029.5,5069.07 9050.5,5090.07 9050.5,5091.05 R232.1@9110.5,5091.05
NetC165_2: C165.2 R259.1 U10.57 | length 256.9
  Layer 1 - Top Layer w10: R259.1@8472.94,5422.44 8527.94,5422.44 8527.94,5421.46 8620.69,5328.71 U10.57@8620.69,5258.94
NetC167_2: C167.2 U10.14 | length 216.2
  Layer 1 - Top Layer w10: U10.14@8348.05,4868.19 8397.81,4868.19 8420.5,4845.5 8420.5,4807.68 C167.2@8352.94,4740.12 C167.2@8352.94,4739.14
NetC168_1: C168.1 U10.56 | length 187.3
  Layer 1 - Top Layer w10: C168.1@8582.94,5422.44 8582.94,5395.11 8640.37,5337.68 U10.56@8640.37,5258.94
NetC169_2: C169.2 U10.59 | length 138
  Layer 1 - Top Layer w10: C169.2@8519.43,5346.94 8561.11,5346.94 8581.32,5326.73 U10.59@8581.32,5258.94
NetC170_2: C170.2 R263.1 U10.55 | length 1325.2
  Layer 1 - Top Layer w10: R263.1@8366.6,4414.05 v1(8366.6,4447.46) ; C170.2@8642.94,5422.44 8642.94,5385.11 v1(8660.06,5367.99) U10.55@8660.06,5258.94
  Bottom Layer w10: v1(8366.6,4447.46) 8366.6,4505.6 8416,4555 8551,4555 8576,4580 8576,5175 8660.06,5259.06 v1(8660.06,5367.99)
NetC171_1: C171.1 R262.2 R263.2 Vtune_TP3.1 | length 301.4
  Layer 1 - Top Layer w10: Vtune_TP3.1@8258.64,4263.16 8334.86,4263.16 8360.75,4289.05 C171.1@8426.6,4289.05 8427.12,4289.57 R262.2@8427.12,4351.06 R263.2@8366.6,4351.06
NetC172_1: C172.1 C175.1 R262.1 U10.22 | length 375.4
  Layer 1 - Top Layer w10: R262.1@8427.12,4414.05 C172.1@8486.6,4414.05 ; C172.1@8484.43,4420.64 8484.43,4477.64 8488.64,4477.64 8581.32,4570.31 U10.22@8581.32,4693.98
NetC172_2: C172.2 R264.1 | length 62
  Layer 1 - Top Layer w10: R264.1@8486.6,4289.05 C172.2@8486.6,4351.06
NetC173_2: C173.2 L22.2 R261.2 R265.1 | length 30.3
  Bottom Layer w20: v1(8729.81,4546.14) L22.2@8729.81,4576.44
NetC174_1: C174.1 U10.44 | length 111.1
  Layer 1 - Top Layer w10: U10.44@8913.01,5045.35 8957.3,5045.35 C174.1@9004.55,5092.6
NetC180_1: C180.1 U10.7 | length 172.3
  Layer 1 - Top Layer w10: C180.1@8208.7,5085.48 C180.1@8209.19,5085.48 8209.68,5085.48 8289.18,5005.98 U10.7@8348.05,5005.98
NetC182_1: C182.1 U10.42 | length 111.9
  Layer 1 - Top Layer w10: v1(8835.5,5005.98) U10.42@8913.01,5005.98
  Bottom Layer w20: v1(8835.5,5005.98) 8868.52,5005.98 C182.1@8869.5,5005
NetC183_1: C183.1 U10.53 | length 163.5
  Layer 1 - Top Layer w10: C183.1@8699.32,5422.44 8699.32,5399.76 8699.43,5399.65 U10.53@8699.43,5258.94
NetC187_2: C187.2 C188.2 J16.1 U2.6@450.36,1330.27 | length 338.5
  Layer 1 - Top Layer w20: v1(420,1330) 450.09,1330 U2.6@450.36,1330.27
  Bottom Layer w20: J16.1@388.62,1055 C187.2@388.62,1285 388.62,1326.06 C188.2@392.56,1330 ; C188.2@388.62,1330 C188.2@392.56,1330 ; v1(420,1330) C188.2@392.56,1330
NetC189_2: C189.2 L19.2 R315.2 R327.1 | length 30.3
  Bottom Layer w20: L19.2@6952.96,8727.4 v1(6983.26,8727.4)
NetC190_1: C190.1 U4.53 | length 163.5
  Layer 1 - Top Layer w10: C190.1@6090.11,8698.82 6112.79,8698.82 6112.9,8698.93 U4.53@6253.61,8698.93
NetC191_1: C191.1 R333.2 R349.2 | length 252.3
  Layer 1 - Top Layer w24: R333.2@6452.47,7990.79 6588.2,8126.51 C191.1@6588.2,8186.91
NetC193_1: C193.1 R281.2 R300.2 | length 252.3
  Layer 1 - Top Layer w24: R281.2@7991.28,5060.08 8127.01,4924.35 8137.87,4924.35 C193.1@8187.41,4924.35
NetC194_1: C194.1 R300.1 R317.1 | length 251.9
  Layer 1 - Top Layer w24: R317.1@7991.26,4737.62 8124.31,4870.67 8185.91,4870.67 C194.1@8187.41,4869.17
NetC195_1: C195.1 R349.1 R354.1 | length 251.9
  Layer 1 - Top Layer w24: C195.1@6643.38,8187.41 6641.88,8185.91 6641.88,8124.31 R354.1@6774.93,7991.25
NetC202_1: C202.1 R324.1 | length 64.5
  Layer 1 - Top Layer w24: C202.1@8728.87,6556.75 R324.1@8793.4,6556.75
NetC203_1: C203.1 C205.1 R373.1 | length 93.2
  Layer 1 - Top Layer w24: C203.1@9285.62,6556.75 R373.1@9378.82,6556.75
NetC203_2: C203.2 U11.13 | length 77
  Layer 1 - Top Layer w24: U11.13@9161.38,6556.75 C203.2@9238.38,6556.75
NetC204_1: C204.1 R326.1 | length 64.5
  Layer 1 - Top Layer w24: C204.1@8728.87,6506.75 R326.1@8793.4,6506.75
NetC206_1: C206.1 C207.1 R374.1 | length 93.2
  Layer 1 - Top Layer w24: C207.1@9285.62,6506.75 R374.1@9378.82,6506.75
NetC207_2: C207.2 U11.12 | length 77
  Layer 1 - Top Layer w24: U11.12@9161.38,6506.75 C207.2@9238.38,6506.75
NetC208_2: C208.2 C209.1 R375.2 U11.8
NetC210_1: C210.1 C211.2 R376.2 U11.3
NetC212_1: C212.1 J42.1 R377.2 R379.2 R380.2 U11.2 | length 466
  Layer 1 - Top Layer w24: U11.2@9063.94,6639.03 9063.94,6770.09 J42.1@9063.94,7105
NetC213_1: C213.1 R378.1 | length 60
  Layer 1 - Top Layer w22: C213.1@9022.44,6276.59 9024.19,6278.34 9024.19,6333.34 R378.1@9025.94,6335.09
NetC217_1: C217.1 R384.1 U21.2 | length 5342.9
  Layer 3 - Signal w10: v1(1790,2770.5) 1800,2780.5 1800,3231.5 1835,3266.5 1835,3357.19 1810,3382.19 1810,3410 1810,3667.8 2100,3957.8 2100,4770 v1(2110,4780)
  Bottom Layer w10: R384.1@1490,6401.42 1538.58,6401.42 1625,6315 1730,6315 1765,6280 2023.28,6280 2100,6203.28 2100,4790 v1(2110,4780) ; v1(1790,2770.5) 1790.5,2770 1950,2770 2025,2695 2210,2695 2235,2720 2235,2770 2290,2825 2569,2825 2594,2800 2594,2774.51 2574.49,2755 C217.1@2573.5,2755 2580,2748.5 U21.2@2580,2679.92
NetC217_2: C217.2 R385.1 U21.3 | length 5255.8
  Layer 3 - Signal w10: v1(1775,2805) 1775,3134.45 1745,3164.45 1745,3230 1775,3260 1775,3375 1790,3390 1790,3676.08 2080,3966.08 2080,4770 v1(2070,4780)
  Bottom Layer w10: R385.1@1490,6315 1490,6308.5 1588.5,6210 1715,6210 1765,6260 2015,6260 2080,6195 2080,4790 v1(2070,4780) ; v1(1775,2805) 1800,2805 1810,2795 2231.05,2795 2281.52,2845.47 2578.53,2845.47 2614.69,2809.31 2614.69,2775.82 2635.51,2755 C217.2@2636.5,2755 2630,2748.5 U21.3@2630,2679.92
NetC223_1: C223.1 C224.2 C225.2 TP16.1 U24.12 | length 418.2
  Layer 1 - Top Layer w12: TP16.1@2245,8195 2312.56,8262.56 2312.56,8440 2307.56,8445 2322.56,8460 U24.12@2322.56,8531.5
  Bottom Layer w12: v1(2314,8400) 2314,8444 C223.1@2315,8445
NetC226_2: C226.2 U25.19 | length 126.9
  Layer 1 - Top Layer w12: C226.2@985,7271.5 985,7325 1004.13,7344.13 1049.2,7344.13 U25.19@1050.08,7345
NetC229_1: C229.1 R409.1 R413.2 | length 146.3
  Layer 1 - Top Layer w12: R409.1@690,7428.5 696.5,7435 R413.2@748.5,7435 748.5,7408 785,7371.5 C229.1@785,7365
NetC239_1: C239.1 TP14.1 U25.16 | length 187.8
  Layer 1 - Top Layer w12: TP14.1@930,7410 935.24,7415.24 952.24,7415.24 965,7428 C239.1@965,7475 ; C239.1@965,7480 C239.1@965,7475 ; U25.16@1050.08,7495 985,7495 C239.1@965,7475
NetC241_1: C241.1 R410.1 R416.2 TP18.1 U24.7 | length 454.7
  Layer 1 - Top Layer w12: TP18.1@2010,9305 2010,9205 2045,9170 R410.1@2050,9170 C241.1@2135,9170 2140,9170 v1(2174,9136) 2185,9125 2195,9125 2222.56,9097.44 U24.7@2222.56,9058.5
  Bottom Layer w12: R416.2@2135,9178.5 2135,9175 v1(2174,9136)
NetC242_1: C242.1 J45.2 R408.1 R417.2 TP15.1 U24.6 | length 727.1
  Layer 1 - Top Layer w12: J45.2@2170,9670 2170,9575 R408.1@2180,9565 TP15.1@2180,9400 2180,9210 2220,9170 C242.1@2225,9170 2225,9135 v1(2235,9125) 2256.35,9125 2272.56,9108.79 U24.6@2272.56,9058.5
  Bottom Layer w12: R417.2@2225,9178.5 2225,9135 v1(2235,9125)
NetC243_1: C243.1 R418.2 TP21.1 U24.5 | length 414.9
  Layer 1 - Top Layer w12: U24.5@2322.56,9058.5 v1(2322.56,9129.99) 2322.56,9162.44 C243.1@2315,9170 2320,9170 2365,9215 TP21.1@2365,9395
  Bottom Layer w12: R418.2@2315,9178.5 2322.56,9170.94 v1(2322.56,9129.99)
NetC244_1: C244.1 R411.1 R421.2 U25.2 | length 231
  Layer 1 - Top Layer w12: U25.2@1509.92,7345 1558.5,7345 1588.5,7315 C244.1@1595,7315 1600,7310 1721.5,7310 R411.1@1725,7313.5
NetC245_1: C245.1 R420.2 U25.18 | length 268.6
  Layer 1 - Top Layer w12: C245.1@865,7280 873.5,7271.5 R420.2@930,7271.5 930,7307 ; 930,7315 930,7307 ; U25.18@1050.08,7395 1018,7395 930,7307
NetC246_2: C246.2 J43.2 TP19.1 U24.11 | length 1514.7
  Layer 1 - Top Layer w12: TP19.1@2080,8405 2146.92,8405 2163.74,8421.82 2199.73,8421.82 C246.2@2210,8432.09 2220.83,8432.09 2256.26,8467.52 2272.56,8483.82 U24.11@2272.56,8531.5
  Bottom Layer w12: TP19.1@2080,8405 2170,8315 2880,8315 2987.56,8422.56 J43.2@2987.56,8675
NetC247_2: C247.2 TP17.1 U24.9 | length 486.1
  Layer 1 - Top Layer w12: TP17.1@1740,8405 1867.91,8532.91 C247.2@2052.56,8532.91 2053.97,8531.5 U24.9@2172.56,8531.5
NetC248_1: C248.1 R420.1 | length 68.5
  Layer 1 - Top Layer w12: C248.1@865,7200 873.5,7208.5 R420.1@930,7208.5
NetC249_1: C249.1 C250.2 C251.2 TP30.1 U27.12 | length 458.9
  Layer 1 - Top Layer w12: U27.12@907.56,8531.5 v1(907.56,8487.66) 907.56,8460 900,8452.44 C251.2@900,8365 900,8323 914,8309 938,8309 1012,8235 TP30.1@1012,8182
  Bottom Layer w12: C249.1@900,8445 907.56,8452.56 v1(907.56,8487.66)
NetC250_1: C250.1 C251.1 C252.1 C253.1 C254.2 R423.1 TP28.1 U27.13 U27.14 U27.15 U27.16 | length 53.4
  Bottom Layer w12: v1(1365,8565) 1365,8515.2 C253.1@1367.56,8512.64
NetC258_1: C258.1 R425.1 R426.2 TP32.1 U27.7 | length 454.7
  Layer 1 - Top Layer w12: TP32.1@595,9305 595,9205 630,9170 R425.1@635,9170 C258.1@720,9170 725,9170 v1(759,9136) 770,9125 780,9125 807.56,9097.44 U27.7@807.56,9058.5
  Bottom Layer w12: R426.2@720,9178.5 720,9175 v1(759,9136)
NetC259_1: C259.1 J48.2 R424.1 R427.2 TP29.1 U27.6 | length 727.1
  Layer 1 - Top Layer w12: J48.2@755,9670 755,9575 R424.1@765,9565 TP29.1@765,9400 765,9210 805,9170 C259.1@810,9170 810,9135 v1(820,9125) 841.35,9125 857.56,9108.79 U27.6@857.56,9058.5
  Bottom Layer w12: R427.2@810,9178.5 810,9135 v1(820,9125)
NetC260_1: C260.1 R479.2 TP35.1 U27.5 | length 414.9
  Layer 1 - Top Layer w12: U27.5@907.56,9058.5 v1(907.56,9129.99) 907.56,9162.44 C260.1@900,9170 905,9170 950,9215 TP35.1@950,9395
  Bottom Layer w12: R479.2@900,9178.5 907.56,9170.94 v1(907.56,9129.99)
NetC261_1: C261.1 R485.2 U29.4 | length 185.2
  Bottom Layer w12: U29.4@1824.09,7538.54 1824.09,7442.56 R485.2@1816.54,7435 1825,7426.54 C261.1@1825,7360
